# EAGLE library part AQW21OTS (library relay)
PhotoMOS Relay NAiS Source: http://www.mew-europe.com/.. pti_en.pdf
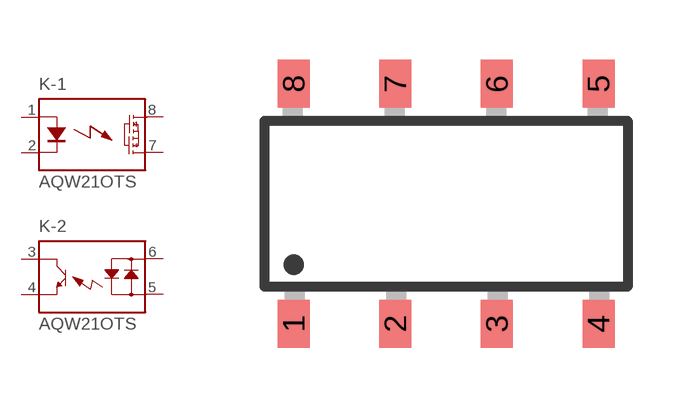
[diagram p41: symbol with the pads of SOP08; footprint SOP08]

Designator prefix K; gates -1=PHOTOMOS_2D -2=PHOTO-DETECTOR

## AQW21OTS (OC_FARNELL: unknown; OC_NEWARK: unknown)  [SOP08]
1  -1:A  pas
2  -1:K  pas
3  -2:K  pas
4  -2:E  pas
5  -2:AC2  pas
6  -2:AC1  pas
7  -1:DS2  pas
8  -1:DS1  pas

## Footprint SOP08 (pad centres in mm)
SOP 08 - AQW21, AQW61 Series NAiS Source: http://www.mew-europe.com/.. pti_en.pdf
smd 0.8 x 1.2: 1 -3.81,-3; 2 -1.27,-3; 3 1.27,-3; 4 3.81,-3; 5 3.81,3; 6 1.27,3; 7 -1.27,3; 8 -3.81,3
